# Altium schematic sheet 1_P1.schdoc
size 431 x 309 mm; Symbol: Sheet-Symbol_A3; Device: Sheet-Symbol_A3; Convert to PCB: yes; Add into BOM: yes; @Project Name: CV工程师专用键盘; @Page Count: 1; @Update Date: 2022-09-08; @Create Date: 2022-08-17; @Schematic Name: Schematic1; @Page No: 1; @Page Name: P1
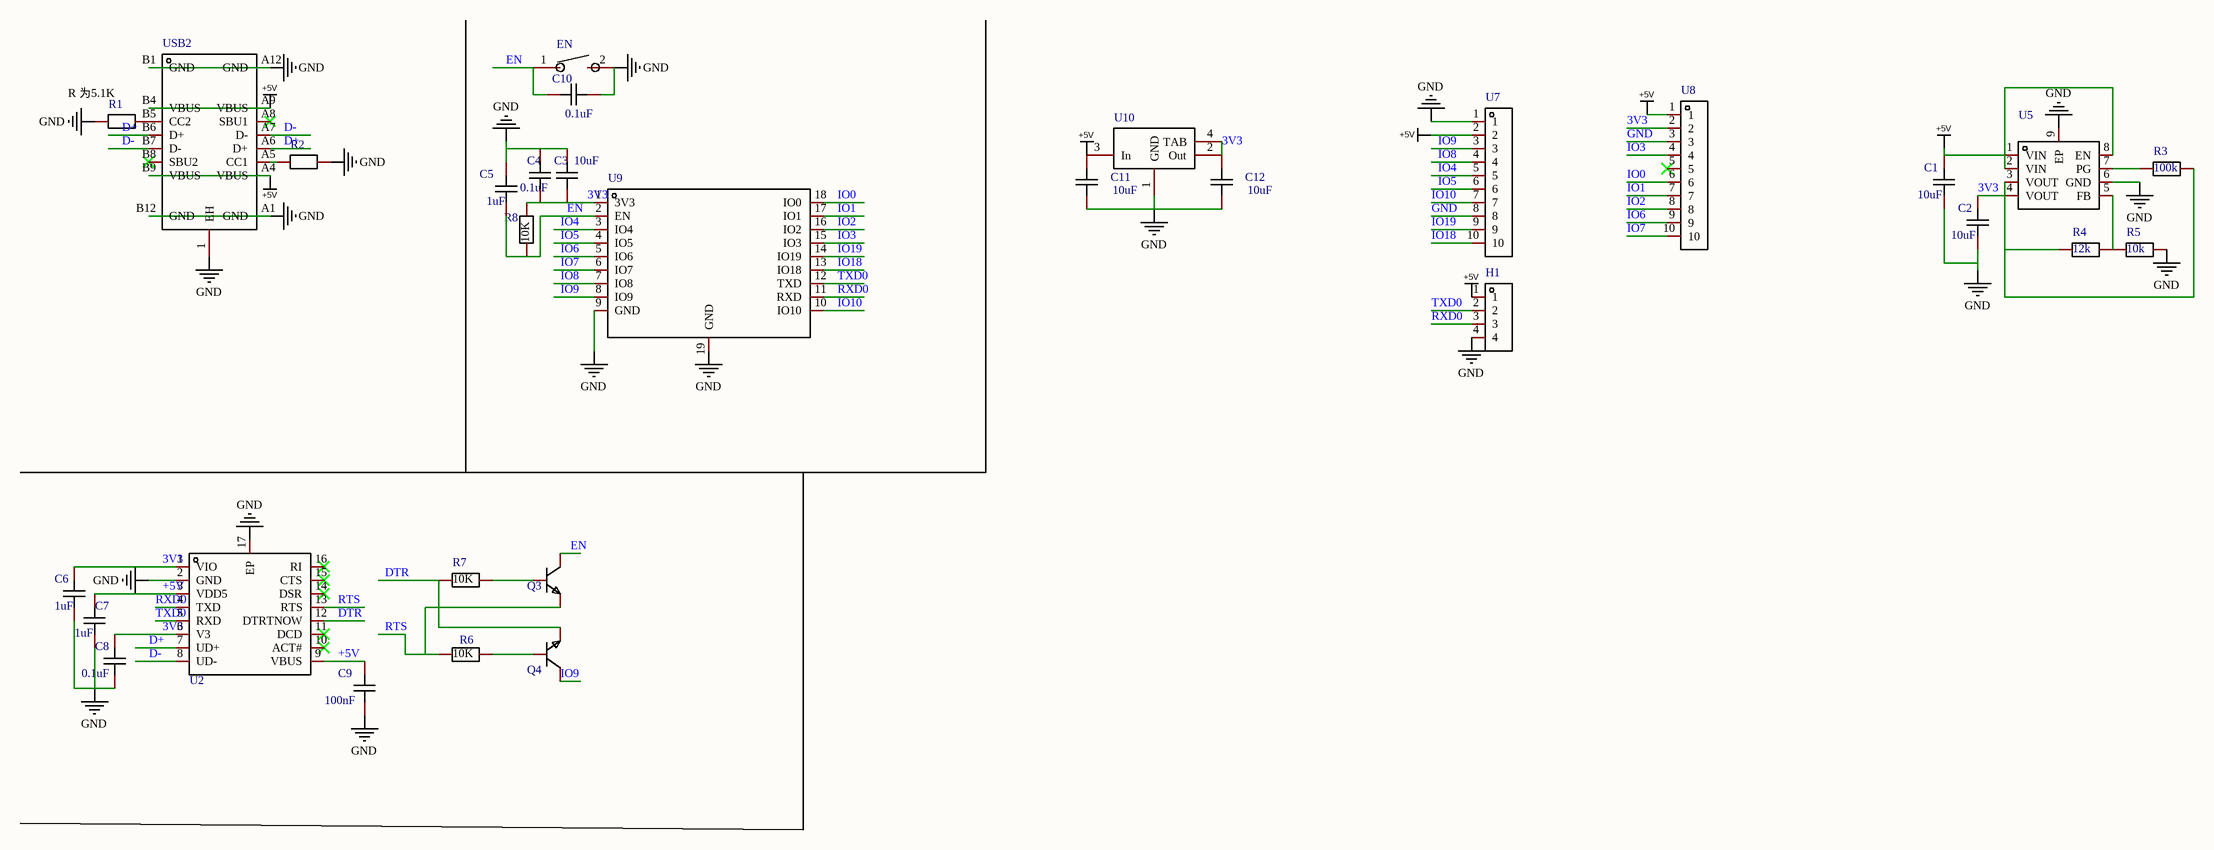
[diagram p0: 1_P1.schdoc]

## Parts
C1  value 10uF  [C0603]  (hidden comment: CC0603KRX7R8BB105)
C2  value 10uF  [C0603]  (hidden comment: CC0603KRX7R8BB105)
C3  value 10uF  (hidden comment: 0603F104Z500CT)
C4  value 0.1uF  (hidden comment: 0603F104Z500CT)
C5  value 1uF  (hidden comment: 0603F104Z500CT)
C6  value 1uF  [C0603]  (hidden comment: CC0603KRX7R8BB105)
C7  value 1uF  [C0603]  (hidden comment: CC0603KRX7R8BB105)
C8  value 0.1uF  [C0603]  (hidden comment: CC0603KRX7R8BB105)
C9  value 100nF  (hidden comment: 0603F104Z500CT)
C10  value 0.1uF  (hidden comment: 0603F104Z500CT)
C11  value 10uF  [C0603]  (hidden comment: JMK107BC6106MA-T)
C12  value 10uF  [C0603]  (hidden comment: JMK107BC6106MA-T)
EN  TSA363G25-250B  (value not drawn)
H1  DIP插件  [HDR-TH_4P-P2.00-V-F]  (value not drawn)
Q3  S8050  (value not drawn)
Q4  S8050  (value not drawn)
R1  0603  [R0603]  (value not drawn)
R2  0603  [R0603]  (value not drawn)
R3  value 100k  (hidden comment: FRC0603F1651TS)
R4  value 12k  (hidden comment: FRC0603F1651TS)
R5  value 10k  (hidden comment: FRC0603F1651TS)
R6  0603  (value not drawn)
R7  0603  (value not drawn)
R8  0603  [R0603]  (value not drawn)
U2  CH343P  [TQFN-16_L3.0-W3.0-P0.50-BL-EP1.7]  (value not drawn)
U5  MP20045DQ  [TDFN-8L_L3.0-W3.0-P0.65-BL-EP]  (value not drawn)
U7  cn10_2r54_10x1  [HDR-TH_10P-P2.54-V-F]  (value not drawn)
U8  cn10_2r54_10x1  [HDR-TH_10P-P2.54-V-F]  (value not drawn)
U9  ESP32-C3-WROOM-02D-N4  [BULETM-SMD_18P-L20.0-W18.0-P1.50_ESP32-C3-WROOM]  (value not drawn)
U10  AMS1117-1.5  [SOT-223-4_L6.5-W3.5-P2.30-LS7.0-BR]  (value not drawn)
USB2  TYPE-C母座16P  (value not drawn)

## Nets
+5V: C1.1 C7.1 C9.2 C11.2 H1.1 U2.3(VDD5) U2.9(VBUS) U5.1(VIN) U5.2(VIN) U5.8(EN) U7.2 U8.1 U10.3(In) USB2.A4(VBUS) USB2.A9(VBUS) USB2.B4(VBUS) USB2.B9(VBUS)
GND: C1.2 C2.2 C3.2 C4.2 C5.2 C6.2 C7.2 C8.2 C9.1 C10.2 C11.1 C12.1 EN.2 H1.4 R1.1 R2.2 R5.2 U2.2(GND) U2.17(EP) U5.6(GND) U5.9(EP) U7.1 U7.8 U8.3 U9.9(GND) U9.19(GND) U10.1(GND) USB2.1(EH) USB2.A1(GND) USB2.A12(GND) USB2.B1(GND) USB2.B12(GND)
3V3: C2.1 C3.1 C4.1 C6.1 C8.1 C12.2 R3.2 R4.1 R8.2 U2.1(VIO) U2.6(V3) U5.3(VOUT) U5.4(VOUT) U8.2 U9.1(3V3) U10.2(Out) U10.4(TAB)
D+: U2.7(UD+) USB2.A6(D+) USB2.B6(D+)
D-: U2.8(UD-) USB2.A7(D-) USB2.B7(D-)
DTR: Q4.2(E) R7.1 U2.12(DTRTNOW)
EN: C5.1 C10.1 EN.1 Q3.3(C) R8.1 U9.2(EN)
IO0: U8.6 U9.18(IO0)
IO1: U8.7 U9.17(IO1)
IO2: U8.8 U9.16(IO2)
IO3: U8.4 U9.15(IO3)
IO4: U7.5 U9.3(IO4)
IO5: U7.6 U9.4(IO5)
IO6: U8.9 U9.5(IO6)
IO7: U8.10 U9.6(IO7)
IO8: U7.4 U9.7(IO8)
IO9: Q4.3(C) U7.3 U9.8(IO9)
IO10: U7.7 U9.10(IO10)
IO18: U7.10 U9.13(IO18)
IO19: U7.9 U9.14(IO19)
RTS: Q3.2(E) R6.1 U2.13(RTS)
RXD0: H1.3 U2.4(TXD) U9.11(RXD)
TXD0: H1.2 U2.5(RXD) U9.12(TXD)
NetQ3_1: Q3.1(B) R7.2
NetQ4_1: Q4.1(B) R6.2
NetR1_2: R1.2 USB2.B5(CC2)
NetR2_1: R2.1 USB2.A5(CC1)
NetR3_1: R3.1 U5.7(PG)
NetR4_2: R4.2 R5.1 U5.5(FB)

Not connected (* = marked no-connect by the designer): U2 10(ACT#)* 11(DCD)* 14(DSR)* 15(CTS)* 16(RI)*; U8 5*; USB2 A8(SBU1)* B8(SBU2)*

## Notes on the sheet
- (near R1) R 为5.1K
- (near R8) 10K
- (near R7) 10K
- (near R6) 10K

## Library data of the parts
C1 C2 C6-C8 = CC0603KRX7R8BB105: 容值:1uF;精度:±10%;额定电压:25V;材质(温度系数):X7R;; Manufacturer: YAGEO(国巨); Add into BOM: yes; Tolerance: ±10%; Voltage Rated: 25V; Temperature Coefficient: X7R
C3-C5 C9 C10 = 0603F104Z500CT: 容值:100nF;精度:-20%~+80%;额定电压:50V;温度系数:Y5V;; Manufacturer: Walsin(华新科); Add into BOM: yes; Voltage Rated: 50V; Temperature Coefficient: Y5V
C11 C12 = JMK107BC6106MA-T: 容值:10uF;精度:±20%;额定电压:-;温度系数:-;; Manufacturer: TAIYO YUDEN(太诱); Add into BOM: yes; Tolerance: ±20%
EN = TSA363G25-250B: 触点电流:50mA;额定电压(DC):12V;绝缘电阻:100MΩ;电路结构:单刀单掷;安装方式:立贴;按钮形状:矩形按钮;按钮/盖帽颜色:白色;带灯:无;作用力:250gf@±50gf;机械寿命:50000;工作温度:-25~+70;引脚样式:鸥翼型;开关长度:6.05mm;开关宽度:3.6mm;开关高度:2.5mm;带支架:否;; Manufacturer: BRIGHT(博瑞泰); Add into BOM: yes; Contact Current: 50mA; Voltage Rating (DC): 12V; Insulation Resistance: 100MΩ; Circuit: 单刀单掷; Actuator Style: 矩形按钮; Actuator/Cap Color: 白色; With Lamp: 无; Mechanical Life: 50000; Pin Style: 鸥翼型; Switch Length: 6.05mm; Switch Width: 3.6mm; Switch Height: 2.5mm; Strike Gundam: 否
H1 = DIP插件: Symbol: DIP插件_C9900022439; Add into BOM: yes
Q3 Q4 = S8050: 晶体管类型:NPN;集射极击穿电压(Vceo):25V;集电极电流(Ic):800mA;功率(Pd):300mW;集电极-发射极饱和电压(VCE(sat)@Ic,Ib):600mV@500mA,50mA;直流电流增益(hFE@Ic,Vce):200@50mA,1V;特征频率(fT):150MHz;工作温度:+150@(Tj);; Manufacturer: HT(金誉); Symbol: S8050_C259988; Add into BOM: yes; Transistor Type: NPN; Collector-Emitter Breakdown Voltage (Vceo): 25V; Collector Current (Ic): 800mA; Power Dissipation (Pd): 300mW; Transition Frequency (fT): 150MHz
R1 R2 R8 = 0603: Symbol: 0603_C9900021178; Add into BOM: yes
R3-R5 = FRC0603F1651TS: 电阻类型:厚膜电阻;阻值:1.65kΩ;精度:±1%;功率:1/10W;温度系数:±100ppm/;最大工作电压:75V;工作温度范围:-55~+155;; Manufacturer: FOJAN(富捷); Add into BOM: yes; Tolerance: ±1%; Power(Watts): 1/10W; Overload Voltage (Max): 75V
R6 R7 = 0603: Symbol: 0603_C9900021181; Add into BOM: yes
U2 = CH343P: 类型:-;协议类别:-;驱动器/接收器数:-;数据速率:-;; Manufacturer: WCH(南京沁恒); Add into BOM: yes
U5 = MP20045DQ: Add into BOM: yes
U7 U8 = cn10_2r54_10x1: Add into BOM: yes
U9 = ESP32-C3-WROOM-02D-N4: Manufacturer: ESPRESSIF 乐鑫; Add into BOM: yes
U10 = AMS1117-1.5: 输出类型:固定;输出极性:正;输出通道数:1;最大输入电压:15V;输出电压:1.5V~1.5V;压差:1.3V@(1A);输出电流:1A;电源纹波抑制比(PSRR):72dB@(120Hz);; Manufacturer: 美国AMS; Add into BOM: yes; Output Type: 固定; Output Polarity: 正; Number of Outputs: 1; Maximum Input Voltage: 15V
USB2 = TYPE-C母座16P: Symbol: TYPE-C母座16P不绣钢; Add into BOM: yes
